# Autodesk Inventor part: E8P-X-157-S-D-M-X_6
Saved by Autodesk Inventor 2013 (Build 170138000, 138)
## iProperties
Created: 2012-07
Part Number: E8P-X-157-S-D-M-X_6
Material: Allgemein
Document SubType Name: Modeling
Designer: rYan
Density: 1 g/cm^3
Mass: 0.0277898 g
Surface Area: 0.805932 cm^2
Volume: 0.0277898 cm^3
Author: rYan
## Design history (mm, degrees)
node "E8P-X-157-S-D-M-X_61"
node "E8P-X-157-S-D-M-X_6"
node "Basis1"
